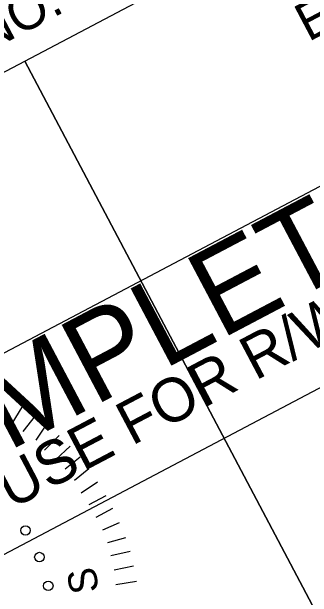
# Model space of a CAD drawing. Extents: x 1486990 to 1489232, y 497582 to 499336.
# Drawn here: x 1488462.5 to 1488502.1, y 499157.9 to 499235.1 of the extents above; entities that cross this region are included whole.
import ezdxf

# ---------------------------------------------------------------- set-up
doc = ezdxf.new("R2010")
doc.units = 0
for name, color, linetype in [('PROF-MAJR', 7, 'Continuous'), ('Prop Drainage Structure Catch Basin Open Throat 1 CELL', 7, 'Continuous'), ('Prop Drainage Structure Drop Inlet Adjust CELL', 7, 'Continuous')]:
    doc.layers.add(name, color=color, linetype=linetype)

msp = doc.modelspace()

# ---------------------------------------------------------------- linework, layer by layer
at = {"layer": 'PROF-MAJR'}
for p, q in [((1488463.866, 499182.965), (1488462.527, 499180.788)), ((1488465.59, 499181.84), (1488463.982, 499179.747)), ((1488467.092, 499180.71), (1488465.706, 499178.622)), ((1488468.78, 499179.227), (1488466.854, 499177.305)), ((1488470.197, 499177.827), (1488468.313, 499176.04)), ((1488471.527, 499176.38), (1488469.549, 499174.771)), ((1488472.679, 499174.84), (1488470.79, 499173.277)), ((1488473.836, 499173.076), (1488471.677, 499171.597)), ((1488474.905, 499171.266), (1488472.695, 499170.099)), ((1488475.793, 499169.586), (1488473.582, 499168.419)), ((1488476.685, 499167.682), (1488474.469, 499166.738)), ((1488477.488, 499165.732), (1488475.133, 499165.053)), ((1488478.11, 499163.911), (1488475.573, 499163.363)), ((1488478.555, 499161.998), (1488476.018, 499161.45)), ((1488478.959, 499159.949), (1488476.239, 499159.531))]:
    msp.add_line(p, q, dxfattribs=at)
for centre in [(1488464.331, 499166.698), (1488466.169, 499163.185), (1488467.33, 499159.393)]:
    msp.add_circle(centre, 0.63, dxfattribs=at)
at = {"layer": 'Prop Drainage Structure Catch Basin Open Throat 1 CELL'}
msp.add_line((1488464.232, 499228.609), (1488516.755, 499129.165), dxfattribs=at)
for points in [[(1488464.232, 499228.609), (1488552.644, 499275.307), (1488605.191, 499175.819), (1488516.767, 499129.115)], [(1488375.758, 499181.893), (1488464.232, 499228.609), (1488516.767, 499129.115), (1488428.293, 499082.427)]]:
    msp.add_lwpolyline(points, close=True, dxfattribs=at)
at = {"layer": 'Prop Drainage Structure Drop Inlet Adjust CELL'}
msp.add_lwpolyline([(1488425.501, 499144.548), (1488414.528, 499165.329), (1488544.519, 499233.968), (1488555.492, 499213.187)], close=True, dxfattribs=at)

# ---------------------------------------------------------------- texts
at = {"layer": 'PROF-MAJR'}
msp.add_text('S', height=3.779, rotation=100.09298, dxfattribs=at).set_placement((1488474.043, 499158.722))
at = {"layer": 'Prop Drainage Structure Catch Basin Open Throat 1 CELL'}
for s, p in [('ENGINEER', (1488501.612, 499231.115)), ('R/W SHEET NO.', (1488424.622, 499211.426))]:
    msp.add_text(s, height=5.0001, rotation=27.8351, dxfattribs=at).set_placement(p)
at = {"layer": 'Prop Drainage Structure Drop Inlet Adjust CELL'}
for s, height, p in [('INCOMPLETE PLANS', 11.52, (1488427.952, 499159.074)), ('DO NOT USE FOR R/W ACQUISITION', 5.76, (1488434.071, 499154.445))]:
    msp.add_text(s, height=height, rotation=27.83509, dxfattribs=at).set_placement(p)

doc.saveas('drawing.dxf')
